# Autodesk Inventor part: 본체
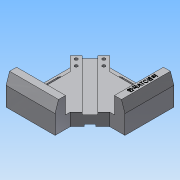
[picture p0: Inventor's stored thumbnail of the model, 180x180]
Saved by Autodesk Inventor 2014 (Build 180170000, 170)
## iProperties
Created: 2020-05
Part Number: 본체
Material: 알루미늄 6061
Document SubType Name: Modeling
Designer: net
Mass: 579.63 g
Surface Area: 410.145 cm^2
Volume: 213.885 cm^3
Density: 2.71 g/cm^3
Appearance: 알루미늄 - 평지
Author: net
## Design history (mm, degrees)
sketch "스케치1"
  geometry: L1 (-60, 60)-(60, 60); L2 (60, 60)-(60, -60); L3 (60, -60)-(-60, -60); L4 (-60, -60)-(-60, 60); L5 (-60, 60)-(60, -60); L6 (60, 60)-(-60, -60); L7 (60, -45)-(-60, -45); L8 (45, 60)-(45, -60); L9 (60, -10)-(38.284, -10); L10 (38.284, -10)-(10, -38.284); L11 (10, -38.284)-(10, -60); L12 (-60, -45)-(-40, -30); L13 (-40, -30)-(-40, 11.716); L14 (-40, 11.716)-(-60, 31.716); L15 (30, 40)-(-11.716, 40); L16 (-11.716, 40)-(-31.716, 60); L17 (-60, 31.716)-(-31.716, 60); L18 (30, 40)-(45, 60); L19 (41.25, 55)-(-26.716, 55); L20 (-55, -41.25)-(-55, 26.716); L21 (22, 48)-(-6, 48); L22 (22, 52)-(-6, 52); L23 (-6, 44)-(22, 44); L24 (-48, -22)-(-48, 6); L25 (-44, -22)-(-44, 6); L26 (-52, 6)-(-52, -22); A1 r 4 centre (22, 48) between (22, 44) and (22, 52); A2 r 4 centre (-6, 48) between (-6, 52) and (-6, 44); A3 r 4 centre (-48, -22) between (-52, -22) and (-44, -22); A4 r 4 centre (-48, 6) between (-44, 6) and (-52, 6); 3 further points
  constraints: 56 end point, 12 point on line, 10 parallel, 9 perpendicular, 8 point on circle, 8 tangent, 4 centre point, 4 midpoint, 1 horizontal
  dimensions: "d16" = 120 distance of L2.end L3.end; "d17" = 120 distance of L1.end L2.end; "d18" = 15 distance between parallel lines of L3 L7; "d19" = 15 distance between parallel lines of L2 L8; "d20" = 50 distance between parallel lines of L3 L9; "d21" = 50 distance between parallel lines of L2 L11; "d23" = 40 distance of L9.end L10.end; "d26" = 15 distance between parallel lines of L20 L13; "d27" = 15 distance between parallel lines of L19 L15; "d28" = 5 distance between parallel lines of L1 L19; "d29" = 5 distance between parallel lines of L4 L20; "d30" = 30 horizontal distance of L1.end L15.start; "d32" = 30 vertical distance of L12.end L3.end; "d33" = 28 distance of L21.end L21.start; "d34" = 8 distance between parallel lines of L22 L23; "d35" = 12 distance from line of L1 L21.start; "d36" = 38 distance from line of L21.start L2; "d37" = 8 diameter of A4; "d38" = 28 distance of L24.end L24.start; "d39" = 38 distance from line of L24.start L3; "d40" = 12 distance from line of L4 L24.start; "d74" = 40 distance of L14.end L16.end
extrude "돌출1" new body sketch "스케치1" distance "d41" = 18; taper "d42" = 0 deg
extrude "돌출2" join sketch "스케치1" distance "d43" = 8; taper "d44" = 0 deg
extrude "돌출3" cut sketch "스케치1" distance "d45" = 18; taper "d46" = 0 deg
extrude "돌출4" join sketch "스케치1" distance "d47" = 42; taper "d48" = 0 deg
extrude "돌출5" cut sketch "스케치1" distance "d49" = 42; taper "d50" = 0 deg
sketch "스케치2"
  geometry: L1 (-40, 0)-(0, 0) reference; L2 (-40, 18)-(0, 18) reference; L3 (-28, 21.5)-(-12, 21.5); L4 (-12, 21.5)-(-12, 14.5); L5 (-12, 14.5)-(-28, 14.5); L6 (-28, 14.5)-(-28, 21.5); L7 (-26, 3)-(-14, 3); L8 (-14, 3)-(-14, -3); L9 (-14, -3)-(-26, -3); L10 (-26, -3)-(-26, 3); 5 further points
  constraints: 16 end point, 4 midpoint, 4 parallel, 2 horizontal, 2 perpendicular, 2 vertical alignment
  dimensions: "d51" = 16 distance of L3.start L3.end; "d52" = 12 distance of L8.end L9.end; "d54" = 3.5 distance between parallel lines of L2 L5; "d56" = 3 distance between parallel lines of L7 L1; "d57" = 7 distance between parallel lines of L5 L3; "d58" = 6 distance between parallel lines of L7 L9
extrude "돌출6" cut sketch "스케치2" stored distance "d59" = 0; taper "d60" = 0 deg
sketch "스케치3"
  geometry: L1 (15, -42)-(0, -42) reference; L2 (15, 0)-(15, -42) reference; L3 (15, -42)-(10, -42); L4 (15, -42)-(15, -27); L5 (15, -27)-(10, -42); 1 further point
  constraints: 6 end point, 2 point on line
  dimensions: "d62" = 5 distance of L1.start L3.end; "d63" = 15 distance of L1.start L4.end
extrude "돌출7" cut sketch "스케치3" stored distance "d64" = 0; taper "d65" = 0 deg
sketch "스케치4"
  geometry: L1 (0, 0)-(42, 0) reference; L2 (42, 15)-(42, 0) reference; L3 (42, 0)-(42, 5); L4 (42, 0)-(27, 0); L5 (27, 0)-(42, 5); 1 further point
  constraints: 6 end point, 2 point on line
  dimensions: "d66" = 5 distance of L1.end L3.end; "d67" = 15 distance of L1.end L4.end
extrude "돌출8" cut sketch "스케치4" stored distance "d68" = 0; taper "d69" = 0 deg
sketch "스케치7"
  geometry: L1 (31.716, 60)-(41.615, 50.101) reference; L2 (26.716, 55)-(31.716, 60) reference; L3 (50.101, 41.615)-(60, 31.716) reference; L4 (50.101, 41.615)-(-19.899, -28.385) reference; L5 (60, 31.716)-(55, 26.716) reference; 5 further points
  dimensions: "d79" = 6 distance from line of point (31.716, 51.515) L1; "d80" = 6 distance from line of L3 point (51.515, 31.716); "d81" = 6 distance from line of point (31.716, 51.515) L2; "d83" = 18 distance from line of point (23.23, 43.029) L1; "d84" = 18 distance from line of point (43.029, 23.23) L3; "d85" = 6 distance from line of point (23.23, 43.029) L2; "d87" = 6 distance from line of point (51.515, 31.716) L5; "d88" = 6 distance from line of point (43.029, 23.23) L5
hole "구멍1" sketch "스케치7" at (31.716, 51.515), (23.23, 43.029), (51.515, 31.716), (43.029, 23.23) diameter "d89" = 4.5; stored, may be unused: countersink angle "d93" = 90 deg, drill point angle "d95" = 0 deg; dims "d90" = 6, "d91" = 8, "d92" = 10, "d94" = 18
sketch "스케치8"
  geometry: L1 (45, 60)-(45, -10) reference; L2 (45, -10)-(55, -10) reference; 2 further points
  constraints: 1 other
  dimensions: "d96" = 5 distance from line of point (50, 25) L1; "d97" = 35 distance from line of point (50, 25) L2
feature "엠보싱1" sketch "스케치8" dims "d98" = 0.5, "d99" = 0
node "솔리드1"
